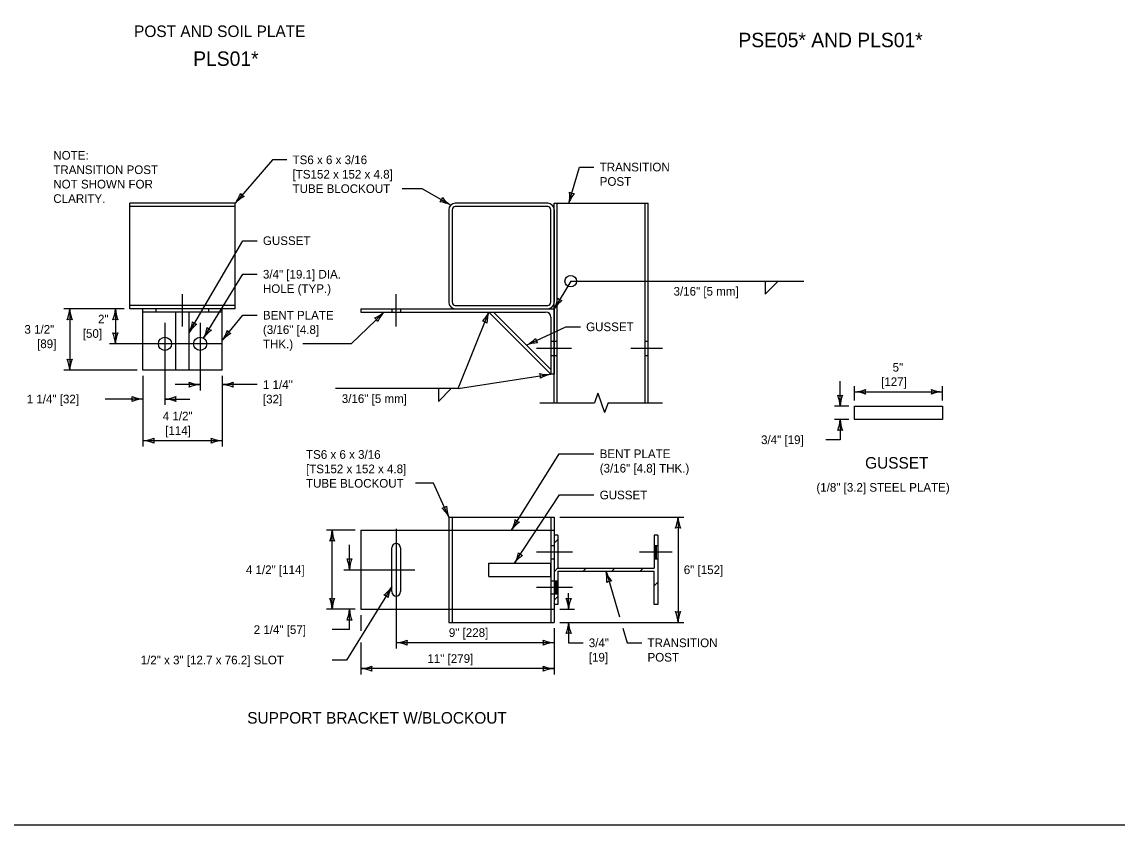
# Model space of a CAD drawing. Extents: x 49991.4 to 50021, y 49987.6 to 50011.4.
# Drawn here: x 50004.46 to 50012.05, y 49987.8 to 49993.37 of the extents above; entities that cross this region are included whole.
import ezdxf

# ---------------------------------------------------------------- set-up
doc = ezdxf.new("R2010")
doc.units = 0
for name, color, linetype in [('Level 1', 7, 'Continuous'), ('Level 2', 7, 'Continuous'), ('Level 3', 7, 'Continuous'), ('Level 4', 7, 'Continuous'), ('Level 5', 7, 'Continuous'), ('Level 6', 7, 'Continuous')]:
    doc.layers.add(name, color=color, linetype=linetype)

msp = doc.modelspace()

# ---------------------------------------------------------------- linework, layer by layer
at = {"layer": 'Level 1'}
for p, q in [((50005.2046, 49991.3794), (50005.2046, 49992.1106)), ((50005.9358, 49992.1106), (50005.2046, 49992.1106)), ((50005.9358, 49991.3794), (50005.9358, 49992.1106)), ((50007.4177, 49992.0659), (50007.4177, 49991.4239)), ((50007.4405, 49992.0659), (50007.4405, 49991.4239)), ((50008.1042, 49992.1105), (50007.4623, 49992.1105)), ((50008.1042, 49992.0877), (50007.4623, 49992.0877)), ((50008.1261, 49991.4239), (50008.1261, 49992.0659)), ((50008.1489, 49992.0659), (50008.1489, 49991.4239)), ((50005.9358, 49991.3794), (50005.2046, 49991.3794)), ((50005.296, 49990.9529), (50005.296, 49991.3794)), ((50005.8444, 49990.9529), (50005.8444, 49991.3794)), ((50006.8083, 49991.3792), (50008.1489, 49991.3792)), ((50006.8083, 49991.3792), (50006.8083, 49991.3564)), ((50007.4623, 49991.4021), (50008.1042, 49991.4021)), ((50008.1489, 49991.3792), (50008.1489, 49990.9252)), ((50005.8444, 49991.3565), (50005.296, 49991.3565)), ((50005.5245, 49990.9529), (50005.5245, 49991.3565)), ((50005.6159, 49990.9529), (50005.6159, 49991.3565)), ((50006.8083, 49991.3564), (50008.0895, 49991.3564)), ((50008.1261, 49990.9252), (50007.6949, 49991.3564)), ((50007.7272, 49991.3564), (50008.1261, 49990.9575)), ((50008.1261, 49991.3198), (50008.1261, 49990.9252)), ((50005.8444, 49990.9529), (50005.296, 49990.9529)), ((50008.1489, 49990.9252), (50008.1261, 49990.9252)), ((50007.4177, 49989.9347), (50008.1489, 49989.9347)), ((50007.4177, 49989.9347), (50007.4177, 49989.8433)), ((50008.1489, 49989.9347), (50008.1489, 49989.2035)), ((50006.8083, 49989.8433), (50008.1489, 49989.8433)), ((50006.8083, 49989.8433), (50006.8083, 49989.2949)), ((50008.1261, 49989.8433), (50008.1261, 49989.2949)), ((50007.0217, 49989.4174), (50007.0217, 49989.7221)), ((50007.0826, 49989.7221), (50007.0826, 49989.4174)), ((50007.6952, 49989.5234), (50007.6952, 49989.6148)), ((50007.6952, 49989.6148), (50008.1243, 49989.6148)), ((50008.1243, 49989.6148), (50008.1243, 49989.5234)), ((50007.6952, 49989.5234), (50008.1243, 49989.5234)), ((50006.8083, 49989.2949), (50008.1489, 49989.2949)), ((50007.4177, 49989.2949), (50007.4177, 49989.2035)), ((50007.4177, 49989.2035), (50008.1489, 49989.2035))]:
    msp.add_line(p, q, dxfattribs=at)
for points in [[(49999.3835, 49998.9992), (50016.7501, 49998.9992), (50016.7501, 49987.7988), (49999.3835, 49987.7988)], [(50010.8421, 49990.7031), (50010.8421, 49990.6117), (50010.2327, 49990.6117), (50010.2327, 49990.7031)]]:
    msp.add_lwpolyline(points, close=True, dxfattribs=at)
for centre in [(50005.4484, 49991.1356), (50005.6921, 49991.1356)]:
    msp.add_circle(centre, 0.0457, dxfattribs=at)
for centre, radius, start, end in [((50007.4623, 49992.0659), 0.0446, 90, 180), ((50007.4623, 49992.0659), 0.0218, 90, 180), ((50008.1042, 49992.0659), 0.0446, 360, 90), ((50008.1042, 49992.0659), 0.0218, 0, 90), ((50007.4623, 49991.4239), 0.0446, 180, 270), ((50007.4623, 49991.4239), 0.0218, 180, 270), ((50008.1042, 49991.4239), 0.0446, 270, 360), ((50008.1042, 49991.4239), 0.0218, 270, 0.08706), ((50008.0895, 49991.3198), 0.0366, 0, 90), ((50007.0521, 49989.7221), 0.0304, 0, 180), ((50007.0521, 49989.4174), 0.0304, 180, 360)]:
    msp.add_arc(centre, radius, start, end, dxfattribs=at)
at = {"layer": 'Level 3'}
for p, q in [((50008.2637, 49991.5702), (50008.1489, 49991.3792)), ((50005.1646, 49991.3794), (50004.7474, 49991.3794)), ((50004.7874, 49991.3794), (50004.7874, 49990.9529)), ((50005.1046, 49991.3794), (50005.1046, 49991.1356)), ((50005.8444, 49991.1581), (50005.9881, 49991.3343)), ((50005.9881, 49991.3343), (50006.0881, 49991.3343)), ((50006.9684, 49991.3564), (50006.7405, 49991.1355)), ((50007.483, 49990.8256), (50007.6949, 49991.3564)), ((50006.7405, 49991.1355), (50006.4038, 49991.1355)), ((50005.256, 49990.9529), (50004.7474, 49990.9529)), ((50007.483, 49990.8256), (50008.1261, 49990.9252)), ((50005.296, 49990.9129), (50005.296, 49990.4248)), ((50005.6921, 49990.8529), (50005.5187, 49990.8529)), ((50005.8444, 49990.9129), (50005.8444, 49990.4248)), ((50006.0881, 49990.8527), (50005.8444, 49990.8527)), ((50010.1327, 49990.7031), (50010.1327, 49990.8765)), ((50010.2327, 49990.7431), (50010.2327, 49990.8431)), ((50010.8421, 49990.7431), (50010.8421, 49990.8431)), ((50010.2327, 49990.8031), (50010.8421, 49990.8031)), ((50005.296, 49990.7529), (50005.0335, 49990.7529)), ((50005.4484, 49990.7529), (50005.6218, 49990.7529)), ((50010.1927, 49990.7031), (50010.0927, 49990.7031)), ((50010.1927, 49990.6117), (50010.0927, 49990.6117)), ((50010.1327, 49990.6117), (50010.1327, 49990.4707)), ((50005.296, 49990.4648), (50005.8444, 49990.4648)), ((50010.1327, 49990.4707), (50010.0327, 49990.4707)), ((50007.853, 49989.8433), (50008.1824, 49990.3733)), ((50008.1824, 49990.3733), (50008.4248, 49990.3733)), ((50008.1889, 49989.9347), (50009.0479, 49989.9347)), ((50009.0079, 49989.9347), (50009.0079, 49989.2035)), ((50006.7683, 49989.8433), (50006.5683, 49989.8433)), ((50006.6083, 49989.2949), (50006.6083, 49989.8433)), ((50006.7283, 49989.5698), (50006.7283, 49989.7432)), ((50007.0217, 49989.45), (50006.7083, 49988.9434)), ((50008.2489, 49989.2949), (50008.2489, 49989.4065)), ((50006.7683, 49989.2949), (50006.5683, 49989.2949)), ((50006.7283, 49989.154), (50006.7283, 49989.2949)), ((50006.8083, 49989.2549), (50006.8083, 49989.145)), ((50008.1889, 49989.2949), (50008.2889, 49989.2949)), ((50008.1889, 49989.2035), (50009.0479, 49989.2035)), ((50008.2489, 49989.2035), (50008.2489, 49989.0626)), ((50006.7283, 49989.154), (50006.6083, 49989.154)), ((50008.1489, 49989.1635), (50008.1489, 49988.8435)), ((50006.8083, 49989.065), (50006.8083, 49988.8435)), ((50008.1489, 49989.0635), (50007.0521, 49989.0635)), ((50008.2489, 49989.0626), (50008.3489, 49989.0626)), ((50006.7083, 49988.9434), (50006.6083, 49988.9434)), ((50008.1489, 49988.8835), (50006.8083, 49988.8835))]:
    msp.add_line(p, q, dxfattribs=at)
for points in [[(50006.2936, 49992.4117), (50006.1936, 49992.4117), (50005.9358, 49992.1106)], [(50008.2504, 49992.1105), (50008.3248, 49992.3616), (50008.4248, 49992.3616)], [(50007.4308, 49992.0975), (50007.2328, 49992.2117), (50007.0942, 49992.2117)], [(50005.6159, 49991.214), (50005.9881, 49991.8511), (50006.0881, 49991.8511)], [(50005.716, 49991.1746), (50005.9881, 49991.6184), (50006.0881, 49991.6184)], [(50008.2637, 49991.5702), (50009.8809, 49991.5702), (50009.8809, 49991.5702)], [(50009.6134, 49991.5702), (50009.6134, 49991.4811), (50009.7026, 49991.5702)], [(50007.9572, 49991.1264), (50008.2304, 49991.2538), (50008.3304, 49991.2538)], [(50007.483, 49990.8256), (50006.7511, 49990.8256), (50006.6309, 49990.8256)], [(50007.3451, 49990.8256), (50007.3451, 49990.7364), (50007.4343, 49990.8256)], [(50007.4177, 49989.9347), (50007.3104, 49990.1687), (50007.1875, 49990.1687)], [(50007.874, 49989.6148), (50008.1848, 49990.0877), (50008.4248, 49990.0877)], [(50008.5084, 49989.5588), (50008.6028, 49989.2419)], [(50008.6257, 49989.1652), (50008.6563, 49989.0626), (50008.7563, 49989.0626)]]:
    msp.add_lwpolyline(points, dxfattribs=at)
msp.add_circle((50008.2637, 49991.5702), 0.0401, dxfattribs=at)
for centre, radius, start, end in [((50005.7516, 49992.2532), 0.233, 322.26257, 341.51242), ((50006.0986, 49991.9592), 0.2223, 116.89127, 137.07478), ((50006.0192, 49992.208), 0.0548, 211.57408, 247.29644), ((50007.3197, 49992.1616), 0.0548, 312.13773, 347.86009), ((50007.5498, 49992.2853), 0.2223, 217.45492, 237.63843), ((50008.024, 49992.1657), 0.233, 346.30516, 5.55501), ((50008.4607, 49992.0386), 0.2223, 140.93386, 161.11737), ((50008.2868, 49992.2335), 0.0548, 235.61667, 271.33903), ((50007.3244, 49991.8902), 0.233, 62.82622, 82.07607), ((50007.9435, 49991.4892), 0.233, 331.81285, 351.0627), ((50008.215, 49991.4891), 0.0548, 221.12436, 256.84672), ((50004.5653, 49991.3886), 0.2223, 337.45601, 357.63952), ((50005.0201, 49991.3909), 0.233, 182.82731, 202.07716), ((50004.8825, 49991.3886), 0.2223, 337.45601, 357.63952), ((50005.3374, 49991.3909), 0.233, 182.82731, 202.07716), ((50008.3346, 49991.2569), 0.2223, 126.44155, 146.62506), ((50004.7874, 49991.2512), 0.0548, 72.13882, 107.86118), ((50005.1046, 49991.2512), 0.0548, 72.13882, 107.86118), ((50006.8203, 49991.5222), 0.2223, 291.56866, 311.75217), ((50006.8763, 49991.2671), 0.0548, 26.25147, 61.97383), ((50007.1386, 49991.1973), 0.233, 136.93996, 156.18981), ((50007.492, 49991.4473), 0.2223, 315.68781, 335.87132), ((50007.9153, 49991.2808), 0.233, 161.05911, 180.30896), ((50005.4092, 49991.3215), 0.233, 332.53192, 351.78177), ((50005.8031, 49991.0941), 0.2223, 127.16062, 147.34413), ((50005.6806, 49991.3247), 0.0548, 221.84343, 257.56579), ((50005.5116, 49991.2864), 0.233, 331.31108, 350.56093), ((50005.9006, 49991.0506), 0.2223, 125.93978, 146.12329), ((50005.783, 49991.2839), 0.0548, 220.62259, 256.34495), ((50005.6575, 49991.2971), 0.233, 323.63582, 342.88567), ((50005.9261, 49991.2583), 0.0548, 212.94733, 248.66969), ((50007.6474, 49991.2373), 0.0548, 50.37062, 86.09298), ((50005.1046, 49991.2638), 0.0548, 252.13882, 287.86118), ((50004.8719, 49991.1241), 0.233, 2.82731, 22.07716), ((50005.3268, 49991.1265), 0.2223, 157.45601, 177.63952), ((50006.0115, 49991.0115), 0.2223, 118.26452, 138.44803), ((50007.8485, 49991.3324), 0.233, 297.82848, 317.07833), ((50008.0734, 49991.1806), 0.0548, 187.13999, 222.86235), ((50008.0428, 49990.9212), 0.2223, 92.45718, 112.64069), ((50004.7874, 49991.0811), 0.0548, 252.13882, 287.86118), ((50004.5547, 49990.9414), 0.233, 2.82731, 22.07716), ((50005.0096, 49990.9437), 0.2223, 157.45601, 177.63952), ((50008.1011, 49991.1461), 0.2223, 256.26, 276.44351), ((50007.9994, 49990.9056), 0.0548, 350.94281, 26.66517), ((50008.1731, 49990.697), 0.233, 101.6313, 120.88115), ((50005.5639, 49990.8529), 0.0548, 342.13882, 17.86118), ((50005.7036, 49991.0856), 0.233, 247.92284, 267.17269), ((50005.7013, 49990.6307), 0.2223, 92.36048, 112.54399), ((50005.833, 49991.0854), 0.233, 272.82731, 292.07716), ((50005.8353, 49990.6305), 0.2223, 67.45601, 87.63952), ((50005.9727, 49990.8527), 0.0548, 162.13882, 197.86118), ((50005.1678, 49990.7529), 0.0548, 342.13882, 17.86118), ((50005.3075, 49990.9856), 0.233, 247.92284, 267.17269), ((50005.4369, 49990.9856), 0.233, 272.82731, 292.07716), ((50005.5766, 49990.7529), 0.0548, 162.13882, 197.86118), ((50010.1327, 49990.8313), 0.0548, 252.13882, 287.86118), ((50009.9, 49990.6916), 0.233, 2.82731, 22.07716), ((50010.3548, 49990.694), 0.2223, 157.45601, 177.63952), ((50010.2212, 49991.0358), 0.233, 272.82731, 292.07716), ((50010.2235, 49990.581), 0.2223, 67.45601, 87.63952), ((50010.3609, 49990.8031), 0.0548, 162.13882, 197.86118), ((50010.8512, 49991.0252), 0.2223, 247.45601, 267.63952), ((50010.7139, 49990.8031), 0.0548, 342.13882, 17.86118), ((50010.8536, 49990.5704), 0.233, 92.82731, 112.07716), ((50005.3052, 49990.5307), 0.2223, 92.36048, 112.54399), ((50005.4392, 49990.5307), 0.2223, 67.45601, 87.63952), ((50009.9, 49990.6232), 0.233, 337.92284, 357.17269), ((50010.3548, 49990.6209), 0.2223, 182.36048, 202.54399), ((50010.1327, 49990.4835), 0.0548, 72.13882, 107.86118), ((50005.2869, 49990.6869), 0.2223, 272.36048, 292.54399), ((50005.2846, 49990.2321), 0.233, 67.92284, 87.17269), ((50005.4243, 49990.4648), 0.0548, 162.13882, 197.86118), ((50005.7162, 49990.4648), 0.0548, 342.13882, 17.86118), ((50005.8559, 49990.6975), 0.233, 247.92284, 267.17269), ((50005.8536, 49990.2426), 0.2223, 92.36048, 112.54399), ((50007.3643, 49990.0513), 0.0548, 276.7618, 312.48416), ((50007.634, 49990.0213), 0.233, 182.54582, 201.79567), ((50007.2196, 49989.8339), 0.2223, 26.98346, 47.16697), ((50008.7858, 49989.9439), 0.2223, 337.45601, 357.63952), ((50009.2406, 49989.9462), 0.233, 182.82731, 202.07716), ((50007.6493, 49989.9564), 0.233, 330.96901, 350.21886), ((50008.0369, 49989.7183), 0.2223, 125.59771, 145.78121), ((50007.9207, 49989.9522), 0.0548, 220.28051, 256.00287), ((50009.0079, 49989.8065), 0.0548, 72.13882, 107.86118), ((50006.3862, 49989.8525), 0.2223, 337.45601, 357.63952), ((50006.841, 49989.8548), 0.233, 182.82731, 202.07716), ((50006.6083, 49989.7151), 0.0548, 72.13882, 107.86118), ((50006.7283, 49989.698), 0.0548, 252.13882, 287.86118), ((50006.4956, 49989.5583), 0.233, 2.82731, 22.07716), ((50006.9504, 49989.5606), 0.2223, 157.45601, 177.63952), ((50007.6733, 49989.7331), 0.233, 329.50749, 348.75734), ((50008.0546, 49989.4852), 0.2223, 124.13619, 144.31969), ((50007.9445, 49989.722), 0.0548, 218.81899, 254.54135), ((50008.2929, 49989.5041), 0.2223, 354.04956, 14.23307), ((50008.7281, 49989.6363), 0.233, 199.42086, 218.67071), ((50008.545, 49989.4359), 0.0548, 88.73237, 124.45473), ((50006.8299, 49989.5822), 0.233, 306.18232, 325.43217), ((50007.2154, 49989.341), 0.2223, 150.61996, 170.80347), ((50006.6083, 49989.4232), 0.0548, 252.13882, 287.86118), ((50006.3756, 49989.2835), 0.233, 2.82731, 22.07716), ((50006.8304, 49989.2858), 0.2223, 157.45601, 177.63952), ((50006.9543, 49989.341), 0.0548, 40.3983, 76.12066), ((50008.2489, 49989.4232), 0.0548, 252.13882, 287.86118), ((50008.0162, 49989.2835), 0.233, 2.82731, 22.07716), ((50008.471, 49989.2858), 0.2223, 157.45601, 177.63952), ((50006.5062, 49989.3041), 0.2223, 337.45601, 357.63952), ((50006.961, 49989.3064), 0.233, 182.82731, 202.07716), ((50009.0079, 49989.3318), 0.0548, 252.13882, 287.86118), ((50008.7752, 49989.1921), 0.233, 2.82731, 22.07716), ((50009.23, 49989.1944), 0.2223, 157.45601, 177.63952), ((50006.7283, 49989.1667), 0.0548, 72.13882, 107.86118), ((50008.0162, 49989.215), 0.233, 337.92284, 357.17269), ((50008.471, 49989.2127), 0.2223, 182.36048, 202.54399), ((50008.2489, 49989.0753), 0.0548, 72.13882, 107.86118), ((50007.0406, 49989.2963), 0.233, 272.82731, 292.07716), ((50007.0429, 49988.8414), 0.2223, 67.45601, 87.63952), ((50007.1803, 49989.0635), 0.0548, 162.13882, 197.86118), ((50008.1581, 49989.2857), 0.2223, 247.45601, 267.63952), ((50008.0207, 49989.0635), 0.0548, 342.13882, 17.86118), ((50008.1604, 49988.8308), 0.233, 92.82731, 112.07716), ((50006.7968, 49989.1163), 0.233, 272.82731, 292.07716), ((50006.7992, 49988.6614), 0.2223, 67.45601, 87.63952), ((50006.9365, 49988.8835), 0.0548, 162.13882, 197.86118), ((50008.1581, 49989.1057), 0.2223, 247.45601, 267.63952), ((50008.0207, 49988.8835), 0.0548, 342.13882, 17.86118), ((50008.1604, 49988.6508), 0.233, 92.82731, 112.07716)]:
    msp.add_arc(centre, radius, start, end, dxfattribs=at)
at = {"layer": 'Level 4'}
for p, q in [((50005.9358, 49992.0878), (50005.2046, 49992.0878)), ((50008.1489, 49992.1105), (50008.801, 49992.1105)), ((50008.1489, 49990.7259), (50008.1489, 49992.1105)), ((50008.1697, 49990.7259), (50008.1697, 49992.1105)), ((50008.7802, 49990.7259), (50008.7802, 49992.1105)), ((50008.801, 49990.7259), (50008.801, 49992.1105)), ((50005.9358, 49991.4022), (50005.2046, 49991.4022)), ((50005.3881, 49991.3565), (50005.3881, 49991.3794)), ((50005.7536, 49991.3565), (50005.7536, 49991.3794)), ((50007.0216, 49991.3792), (50007.0216, 49991.3564)), ((50007.0826, 49991.3792), (50007.0826, 49991.3564)), ((50008.1261, 49991.1552), (50008.1697, 49991.1552)), ((50008.7802, 49991.1552), (50008.801, 49991.1552)), ((50008.1261, 49991.0559), (50008.1697, 49991.0559)), ((50008.7802, 49991.0559), (50008.801, 49991.0559)), ((50007.4405, 49989.9347), (50007.4405, 49989.2035)), ((50008.1261, 49989.9347), (50008.1261, 49989.2035)), ((50007.4177, 49989.8433), (50007.4177, 49989.2949)), ((50008.1751, 49989.8092), (50008.1489, 49989.8092)), ((50008.1489, 49989.7539), (50008.1751, 49989.7801)), ((50008.1751, 49989.8092), (50008.1751, 49989.5795)), ((50008.8417, 49989.8092), (50008.8417, 49989.5795)), ((50008.8679, 49989.8092), (50008.8417, 49989.8092)), ((50008.8679, 49989.8092), (50008.8679, 49989.3291)), ((50008.1261, 49989.7367), (50008.1489, 49989.7367)), ((50008.8417, 49989.7367), (50008.8679, 49989.7367)), ((50008.8504, 49989.6453), (50008.8504, 49989.7367)), ((50008.8592, 49989.6453), (50008.8592, 49989.7367)), ((50008.1261, 49989.6453), (50008.1489, 49989.6453)), ((50008.8417, 49989.6453), (50008.8679, 49989.6453)), ((50008.1489, 49989.5559), (50008.1751, 49989.5821)), ((50008.1751, 49989.5795), (50008.8417, 49989.5795)), ((50008.1751, 49989.5588), (50008.8417, 49989.5588)), ((50008.1751, 49989.5588), (50008.1751, 49989.3291)), ((50008.3498, 49989.5588), (50008.3705, 49989.5795)), ((50008.5478, 49989.5588), (50008.5685, 49989.5795)), ((50008.7457, 49989.5588), (50008.7665, 49989.5795)), ((50008.8417, 49989.3291), (50008.8417, 49989.5588)), ((50008.1261, 49989.493), (50008.1751, 49989.493)), ((50008.1576, 49989.4016), (50008.1576, 49989.493)), ((50008.1664, 49989.4016), (50008.1664, 49989.493)), ((50008.8417, 49989.4568), (50008.8679, 49989.483)), ((50008.1261, 49989.4016), (50008.1751, 49989.4016)), ((50008.1489, 49989.3579), (50008.1751, 49989.3841)), ((50008.1751, 49989.3291), (50008.1489, 49989.3291)), ((50008.8679, 49989.3291), (50008.8417, 49989.3291))]:
    msp.add_line(p, q, dxfattribs=at)
at = {"layer": 'Level 5'}
for p, q in [((50005.5709, 49991.2565), (50005.5709, 49991.4794)), ((50007.0521, 49991.2564), (50007.0521, 49991.4792)), ((50005.4484, 49991.2813), (50005.4484, 49990.7129)), ((50005.6921, 49991.2813), (50005.6921, 49990.8129)), ((50005.8378, 49991.1356), (50005.0646, 49991.1356)), ((50008.0261, 49991.1055), (50008.2697, 49991.1055)), ((50008.6802, 49991.1055), (50008.901, 49991.1055)), ((50007.0522, 49989.8525), (50007.052, 49989.0235)), ((50008.2751, 49989.691), (50008.0261, 49989.691)), ((50008.9679, 49989.691), (50008.7417, 49989.691)), ((50006.6883, 49989.5698), (50007.1826, 49989.5698)), ((50008.2751, 49989.4473), (50008.0261, 49989.4473))]:
    msp.add_line(p, q, dxfattribs=at)
at = {"layer": 'Level 6'}
for p, q in [((50008.4513, 49990.7928), (50008.4276, 49990.7259)), ((50008.4513, 49990.7928), (50008.4749, 49990.7259)), ((50008.0489, 49990.7259), (50008.4276, 49990.7259)), ((50008.4749, 49990.7259), (50008.4986, 49990.6591)), ((50008.5223, 49990.7259), (50008.4986, 49990.6591)), ((50008.5223, 49990.7259), (50008.901, 49990.7259))]:
    msp.add_line(p, q, dxfattribs=at)

# ---------------------------------------------------------------- texts
at = {"layer": 'Level 2'}
for s, height, p in [('POST AND SOIL PLATE', 0.08, (50005.2341, 49993.2633)), ('PSE05* AND PLS01*', 0.1, (50009.427, 49993.1927)), ('PLS01*', 0.1, (50005.6445, 49993.0633)), ('NOTE:', 0.06, (50004.6738, 49992.413)), ('TRANSITION POST', 0.06, (50004.6738, 49992.313)), ('TRANSITION', 0.06, (50008.4648, 49992.3316)), ('POST', 0.06, (50008.4648, 49992.2316)), ('NOT SHOWN FOR', 0.06, (50004.6738, 49992.213)), ('CLARITY.', 0.06, (50004.6738, 49992.113)), ('3/16" [5 mm]', 0.06, (50008.9769, 49991.4702)), ('1 1/4"', 0.06, (50006.1281, 49990.8227)), ('1 1/4" [32]', 0.06, (50004.489, 49990.7229)), ('[32]', 0.06, (50006.1281, 49990.7227)), ('3/16" [5 mm]', 0.06, (50006.6752, 49990.7256)), ('GUSSET', 0.08, (50010.3061, 49990.2705)), ('TRANSITION', 0.06, (50008.7963, 49989.0326)), ('POST', 0.06, (50008.7963, 49988.9326)), ('SUPPORT BRACKET W/BLOCKOUT', 0.08, (50006.0193, 49988.5023))]:
    msp.add_text(s, height=height, dxfattribs=at).set_placement(p)
for s, p in [('TS6 x 6 x 3/16', (50006.3336, 49992.3817)), ('[TS152 x 152 x 4.8]', (50006.3336, 49992.2817)), ('TUBE BLOCKOUT', (50006.3336, 49992.1817)), ('GUSSET', (50006.1281, 49991.8211)), ('3/4" [19.1] DIA.', (50006.1281, 49991.5884)), ('HOLE (TYP.)', (50006.1281, 49991.4884)), ('2"', (50004.984, 49991.2775)), ('BENT PLATE', (50006.1281, 49991.3043)), ('3 1/2"', (50004.4733, 49991.2061)), ('[50]', (50004.8781, 49991.1775)), ('(3/16" [4.8]', (50006.1281, 49991.2043)), ('GUSSET', (50008.3704, 49991.2238)), ('[89]', (50004.5609, 49991.1061)), ('THK.)', (50006.1281, 49991.1043)), ('5"', (50010.497, 49990.9431)), ('[127]', (50010.4172, 49990.8431)), ('4 1/2"', (50005.4332, 49990.6048)), ('[114]', (50005.45, 49990.5048)), ('3/4" [19]', (50009.5841, 49990.4407)), ('TS6 x 6 x 3/16 ', (50006.427, 49990.3387)), ('BENT PLATE', (50008.4648, 49990.3433)), ('[TS152 x 152 x 4.8]', (50006.427, 49990.2387)), ('(3/16" [4.8] THK.)', (50008.4648, 49990.2433)), ('TUBE BLOCKOUT', (50006.427, 49990.1387)), ('(1/8" [3.2] STEEL PLATE)', (50009.9681, 49990.1105)), ('GUSSET', (50008.4648, 49990.0577)), ('4 1/2" [114]', (50006.0099, 49989.5391)), ('6" [152]', (50009.0479, 49989.5391)), ('2 1/4" [57]', (50006.0638, 49989.124)), ('9" [228]', (50007.418, 49989.1035)), ('3/4"', (50008.3889, 49989.0326)), ('1/2" x 3" [12.7 x 76.2] SLOT', (50005.2798, 49988.9134)), ('11" [279]', (50007.2692, 49988.9235)), ('[19]', (50008.3889, 49988.9326))]:
    msp.add_text(s, height=0.06, rotation=360, dxfattribs=at).set_placement(p)

doc.saveas('drawing.dxf')
